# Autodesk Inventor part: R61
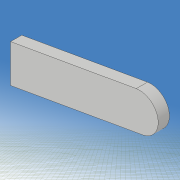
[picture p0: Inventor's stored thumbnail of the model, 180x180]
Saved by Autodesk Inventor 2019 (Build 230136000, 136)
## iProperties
Created: 2021-05
Part Number: R61
Material: 一般
Document SubType Name: Modeling
Designer: kikut
Density: 1 g/cm^3
Appearance: 既定
Mass: 0.0080537 g
Surface Area: 0.40893 cm^2
Volume: 0.0080537 cm^3
Author: kikut
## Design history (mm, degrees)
sketch "スケッチ1"
  geometry: L1 (80, 60)-(-80, 60); L2 (-80, 60)-(-80, -60); L3 (-80, -60)-(80, -60); L4 (80, -60)-(80, 60); L5 (80, 60)-(-80, -60); L6 (-80, 60)-(80, -60); 1 further point
  constraints: 12 end point, 2 midpoint, 2 parallel, 1 horizontal, 1 perpendicular
  dimensions: "d0" = 160 distance of L2.end L3.end; "d1" = 120 distance of L1.end L2.end
extrude "押し出し1" new body sketch "スケッチ1" stored distance "d2" = 0.6; taper "d3" = 0 deg
sketch "スケッチ2"
  geometry: L1 (-140, 0)-(140, 0) reference; L2 (0, -54)-(20, -30); L3 (0, 54)-(20, 30); L4 (0, -3)-(6.514, -3); L5 (6.514, -3)-(16, -6); L6 (16, -6)-(24, -3); L7 (24, -3)-(33.716, -3); L8 (0, 3)-(6.514, 3); L9 (6.514, 3)-(16, 6); L10 (16, 6)-(24, 3); L11 (24, 3)-(33.716, 3); L12 (0, -98)-(0, 98) reference; L13 (-100, -70)-(100, -70); L14 (100, -70)-(100, 70); L15 (100, 70)-(-100, 70); L16 (-100, 70)-(-100, -70); L17 (-100, -70)-(100, 70); L18 (100, -70)-(-100, 70); A1 r 60 centre (54.312, 28.5) between (0, 54) and (0, 3); A2 r 60 centre (54.312, -28.5) between (0, -3) and (0, -54); A3 r 18.111 centre (18, -12) between (20, -30) and (33.716, -3); A4 r 18.111 centre (18, 12) between (33.716, 3) and (20, 30); 1 further point
  constraints: 32 end point, 8 point on circle, 8 symmetric about line, 4 centre point, 3 horizontal, 2 collinear, 2 midpoint, 2 parallel, 1 perpendicular
  dimensions: "d5" = 60 radius of A1; "d6" = 6 distance of L8.start L4.start; "d7" = 108 distance of L3.start L2.start; "d8" = 0 horizontal distance of L3.start L8.start; "d9" = 60 distance of L3.end L2.end; "d10" = 0 horizontal distance of point (0, 0) L3.start; "d11" = 20 horizontal distance of L3.start L3.end; "d12" = 24 distance of A4.centre A3.centre; "d13" = 6 distance of L11.end L7.end; "d14" = 12 distance of L9.end L5.end; "d15" = 16 distance from line of L12 L5.end; "d16" = 24 distance from line of L6.end L12; "d17" = 200 distance of L14.end L15.end; "d18" = 140 distance of L15.end L13.start; "d30" = 18 distance from line of L12 A4.centre
extrude "押し出し2" cut sketch "スケッチ2" stored distance "d19" = 10; taper "d20" = 0 deg
sketch "スケッチ3"
  geometry: L1 (49.705, -17.97)-(33.948, -15.191); L2 (33.948, -15.191)-(34.295, -13.222); L3 (34.295, -13.222)-(50.052, -16); L4 (50.052, -16)-(49.705, -17.97); L5 (49.705, -17.97)-(34.295, -13.222); L6 (33.948, -15.191)-(50.052, -16); L7 (50.052, 16)-(34.295, 13.222); L8 (34.295, 13.222)-(33.948, 15.191); L9 (33.948, 15.191)-(49.705, 17.97); L10 (49.705, 17.97)-(50.052, 16); L11 (50.052, 16)-(33.948, 15.191); L12 (34.295, 13.222)-(49.705, 17.97); L13 (-112, 0)-(112, 0) reference; L14 (0, -84)-(0, 84) reference; 3 further points
  constraints: 24 end point, 4 midpoint, 4 parallel, 2 perpendicular, 2 symmetric about line
  dimensions: "d21" = 2 distance of L3.end L1.start; "d22" = 2 distance of L9.end L7.start; "d23" = 16 distance of L8.end L9.end; "d24" = 42 distance from line of L14 point (42, 15.596); "d26" = 10 deg angle of L7 L13; "d62" = 16 distance from line of L3.end L13
extrude "押し出し3" join sketch "スケッチ3" distance "d27" = 0.6; taper "d28" = 0 deg
fillet "フィレット1" dims "d31" = 2
fillet "フィレット2" dims "d32" = 1
sketch "スケッチ6"
  geometry: L1 (-20, 60)-(80, 60); L2 (80, 60)-(80, -60); L3 (80, -60)-(-20, -60); L4 (-20, -60)-(-20, 60); L5 (-46.168, 0)-(93.832, 0) reference; L6 (0, -84)-(0, 84) reference; L7 (42, 10)-(50, 10); L8 (50, 10)-(50, 20); L9 (50, 20)-(42, 20); L10 (42, 20)-(42, 10); 1 further point
  constraints: 16 end point, 4 parallel, 2 horizontal, 2 perpendicular, 1 other
  dimensions: "d63" = 120 distance of L3.end L1.start; "d64" = 100 distance of L1.start L1.end; "d65" = 20 distance between parallel lines of L6 L4; "d66" = 8 distance of L8.end L9.end; "d73" = 10 distance of L9.end L7.start; "d74" = 10 distance between parallel lines of L7 L5; "d75" = 62 distance between parallel lines of L10 L4
extrude "押し出し4" cut sketch "スケッチ6" stored distance "d70" = 10; taper "d71" = 0 deg
node "ソリッド1"
